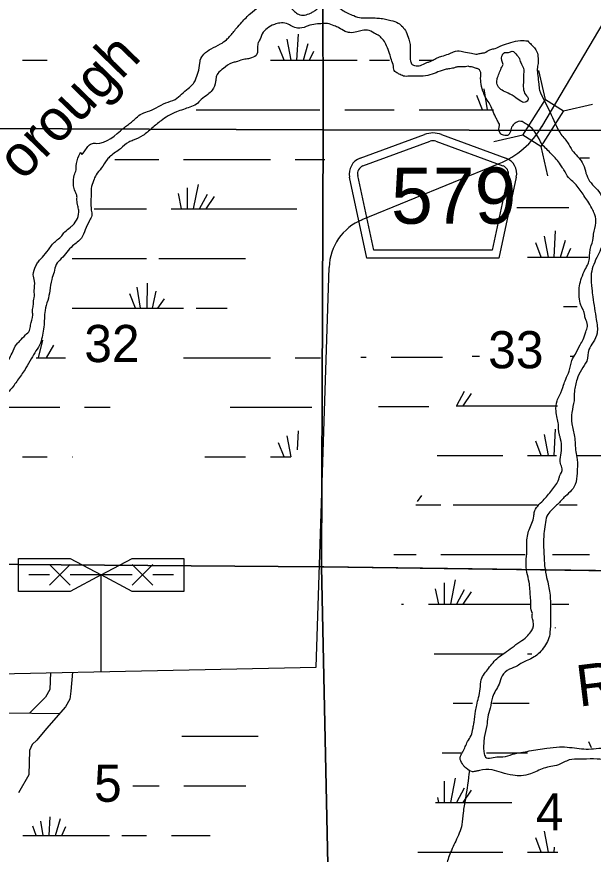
# Model space of a CAD drawing. Extents: x 380424 to 701066, y 1117407 to 1412949.
# Drawn here: x 549442 to 556420, y 1359814 to 1369950 of the extents above; entities that cross this region are included whole.
import ezdxf

# ---------------------------------------------------------------- set-up
doc = ezdxf.new("R2010")
doc.units = 0
for name, color, linetype in [('Bridges and Drawbridges County Highways', 7, 'Continuous'), ('County Routes Highway Center Lines', 7, 'Continuous'), ('Islands', 7, 'Continuous'), ('Local Roads Improved', 7, 'Continuous'), ('Local Roads Paved', 7, 'Continuous'), ('Local Roads Related Cells', 7, 'Continuous'), ('Narrow River Creek and Branch and Slough', 7, 'Continuous'), ('Narrow River Creek and Branch and Slough Text', 7, 'Continuous'), ('Roadshields County Roads', 7, 'Continuous'), ('Section Lines', 7, 'Continuous'), ('Section Numbers', 7, 'Continuous'), ('Swamps', 7, 'Continuous'), ('Township  and Range lines', 7, 'Continuous'), ('Wide Rivers and Canals', 7, 'Continuous')]:
    doc.layers.add(name, color=color, linetype=linetype)

msp = doc.modelspace()

# ---------------------------------------------------------------- linework, layer by layer
at = {"layer": 'Bridges and Drawbridges County Highways'}
for p, q in [((555842, 1368948), (555761, 1369301)), ((556058, 1368812), (556411, 1368892)), ((555569, 1368515), (555216, 1368435)), ((555785, 1368378), (555865, 1368025))]:
    msp.add_line(p, q, dxfattribs=at)
msp.add_lwpolyline([(555569, 1368515), (555842, 1368948), (556058, 1368812), (555785, 1368378)], close=True, dxfattribs=at)
at = {"layer": 'County Routes Highway Center Lines'}
for p, q in [((555799, 1368619), (564285, 1382989)), ((553622, 1367494), (555281, 1368172))]:
    msp.add_line(p, q, dxfattribs=at)
msp.add_lwpolyline([(547296, 1361959), (553065, 1362077), (553222, 1366917)], dxfattribs=at)
for centre, radius, start, end in [((554874, 1369165), 1073, 292.2404, 329.4344), ((553867, 1366896), 645, 112.2402, 178.1451)]:
    msp.add_arc(centre, radius, start, end, dxfattribs=at)
at = {"layer": 'Islands'}
msp.add_spline([(555328, 1369372), (555273, 1369247), (555262, 1369215), (555252, 1369162), (555273, 1369099), (555410, 1369014), (555463, 1368983), (555537, 1368930), (555595, 1368914), (555632, 1368951), (555600, 1369009), (555574, 1369083), (555574, 1369173), (555574, 1369231), (555574, 1369326), (555542, 1369395), (555521, 1369453), (555495, 1369484), (555437, 1369532), (555394, 1369516), (555347, 1369516), (555315, 1369474), (555328, 1369372)], degree=3, dxfattribs=at)
at = {"layer": 'Local Roads Improved'}
msp.add_line((550464, 1362024), (550464, 1363195), dxfattribs=at)
at = {"layer": 'Local Roads Paved'}
for points in [[(549274, 1362000), (549288, 1361524), (549965, 1361519)], [(550117, 1362017), (550096, 1361786), (550083, 1361691), (550034, 1361597), (549804, 1361338), (549685, 1361194), (549628, 1361141), (549595, 1361071), (549587, 1360775), (549463, 1360557)], [(549850, 1362012), (549841, 1361806), (549792, 1361716), (549598, 1361521)]]:
    msp.add_lwpolyline(points, dxfattribs=at)
at = {"layer": 'Local Roads Related Cells'}
for p, q in [((549464, 1363395), (550089, 1363395)), ((549464, 1362995), (549464, 1363395)), ((549839, 1363070), (550089, 1363320)), ((550089, 1363070), (549839, 1363320)), ((550089, 1363395), (550464, 1363195)), ((550464, 1363195), (550839, 1363395)), ((550839, 1363395), (551464, 1363395)), ((551089, 1363072), (550839, 1363322)), ((550839, 1363070), (551089, 1363320)), ((551464, 1363395), (551464, 1362995)), ((549839, 1363195), (549589, 1363195)), ((550464, 1363195), (550089, 1362995)), ((550839, 1363195), (550089, 1363195)), ((550839, 1362995), (550464, 1363195)), ((551339, 1363195), (551089, 1363195)), ((550089, 1362995), (549464, 1362995)), ((551464, 1362995), (550839, 1362995))]:
    msp.add_line(p, q, dxfattribs=at)
at = {"layer": 'Narrow River Creek and Branch and Slough'}
msp.add_spline([(554921, 1360827), (554872, 1360485), (554845, 1360316), (554829, 1360173), (554755, 1359973), (554676, 1359793), (554629, 1359640), (554597, 1359524), (554587, 1359403), (554581, 1359281), (554565, 1359160), (554565, 1359049), (554555, 1358922), (554523, 1358780), (554481, 1358680), (554428, 1358595), (554338, 1358495), (554238, 1358373), (554127, 1358178), (553980, 1358046), (553805, 1357914), (553700, 1357798), (553594, 1357698), (553473, 1357619), (553362, 1357587), (553177, 1357545), (553040, 1357508), (552950, 1357481), (552792, 1357471), (552628, 1357492), (552528, 1357508), (552438, 1357497), (552359, 1357481), (552248, 1357450), (552158, 1357402), (552074, 1357349), (551895, 1357254), (551757, 1357186), (551599, 1357123), (551472, 1357075), (551346, 1357043), (551224, 1357012), (551145, 1356991), (551013, 1356964), (550776, 1356932), (550649, 1356932), (550438, 1356954), (550374, 1356964), (550253, 1356980), (550105, 1357022), (550021, 1357075), (549926, 1357154), (549773, 1357260), (549667, 1357334), (549540, 1357423), (549356, 1357529), (549197, 1357608), (549055, 1357666), (548918, 1357708), (548722, 1357761), (548553, 1357798), (548448, 1357830), (548300, 1357877), (548168, 1357914), (548015, 1357946), (547909, 1357967), (547820, 1357978), (547725, 1357993), (547640, 1358025), (547566, 1358067), (547455, 1358189), (547376, 1358289), (547334, 1358342), (547165, 1358505), (547102, 1358590), (547065, 1358653), (546975, 1358732), (546901, 1358764), (546811, 1358790), (546690, 1358806), (546484, 1358796), (546342, 1358790), (546199, 1358801), (546109, 1358827), (546020, 1358854), (545940, 1358852), (545818, 1358840), (545648, 1358809), (545570, 1358785), (545472, 1358743), (545387, 1358706), (545315, 1358688), (545254, 1358670), (545157, 1358639), (545004, 1358566)], degree=3, dxfattribs=at)
at = {"layer": 'Roadshields County Roads'}
for p, q in [((553598, 1368238), (554377, 1368525)), ((554584, 1368525), (555362, 1368239)), ((553632, 1368144), (554446, 1368443)), ((554515, 1368443), (555327, 1368145)), ((553681, 1367026), (553471, 1368009)), ((553762, 1367126), (553569, 1368029)), ((555391, 1368030), (555197, 1367126)), ((555488, 1368009), (555278, 1367026)), ((555197, 1367126), (553762, 1367126)), ((555278, 1367026), (553681, 1367026))]:
    msp.add_line(p, q, dxfattribs=at)
for centre, radius, start, end in [((554480, 1368243), 300, 69.8262, 110.1722), ((554480, 1368349), 100, 69.8262, 110.1722), ((553667, 1368050), 200, 110.1722, 192.0991), ((555293, 1368051), 200, 347.8993, 69.8262), ((553667, 1368050), 100, 110.1722, 192.0991), ((555293, 1368051), 100, 347.8993, 69.8262)]:
    msp.add_arc(centre, radius, start, end, dxfattribs=at)
at = {"layer": 'Section Lines'}
for points in [[(553140, 1373844), (553151, 1368591), (553151, 1368582), (547887, 1368603), (547887, 1368608), (547882, 1373902)], [(558414, 1373917), (558449, 1368570), (553151, 1368582), (553151, 1368591), (553140, 1373844)], [(553151, 1368582), (553132, 1363292), (547875, 1363334), (547887, 1368603)], [(558449, 1368570), (558542, 1363220), (553159, 1363292), (553132, 1363292), (553151, 1368582)], [(553132, 1363292), (553244, 1357982), (553243, 1357961), (547939, 1358045), (547875, 1363334)], [(558542, 1363220), (558555, 1357902), (553243, 1357961), (553244, 1357982), (553132, 1363292), (553159, 1363292)]]:
    msp.add_lwpolyline(points, close=True, dxfattribs=at)
at = {"layer": 'Swamps'}
for p, q in [((552834, 1369423), (552851, 1369739)), ((552678, 1369423), (552612, 1369595)), ((552763, 1369423), (552717, 1369677)), ((552911, 1369423), (552969, 1369627)), ((552987, 1369423), (553036, 1369532)), ((549512, 1369423), (549812, 1369423)), ((552512, 1369423), (553562, 1369423)), ((553712, 1369423), (553955, 1369423)), ((554312, 1369423), (554485, 1369423)), ((555078, 1368824), (555012, 1368997)), ((555140, 1368823), (555101, 1369076)), ((551612, 1368823), (553112, 1368823)), ((553412, 1368823), (554012, 1368823)), ((554312, 1368823), (554912, 1368823)), ((554912, 1368823), (555214, 1368823)), ((550712, 1368223), (551162, 1368223)), ((551462, 1368223), (552512, 1368223)), ((556260, 1368241), (556375, 1368241)), ((551503, 1367881), (551503, 1367623)), ((551636, 1367918), (551577, 1367623)), ((551395, 1367809), (551432, 1367623)), ((551745, 1367797), (551651, 1367622)), ((551830, 1367773), (551730, 1367624)), ((550712, 1367623), (551012, 1367623)), ((555876, 1367041), (555829, 1367295)), ((555947, 1367041), (555964, 1367357)), ((555791, 1367041), (555725, 1367213)), ((556023, 1367041), (556082, 1367245)), ((556100, 1367041), (556149, 1367149)), ((550112, 1367023), (550712, 1367023)), ((550712, 1367023), (551012, 1367023)), ((551162, 1367023), (552212, 1367023)), ((555625, 1367041), (556359, 1367041)), ((550940, 1366423), (550901, 1366676)), ((551019, 1366423), (551024, 1366727)), ((550878, 1366424), (550812, 1366597)), ((551086, 1366423), (551129, 1366629)), ((551148, 1366422), (551232, 1366536)), ((550112, 1366423), (550712, 1366423)), ((550712, 1366423), (551462, 1366423)), ((549889, 1365977), (549799, 1365823)), ((551462, 1365823), (552512, 1365823)), ((553972, 1365831), (554422, 1365831)), ((554955, 1365841), (555043, 1365841)), ((556142, 1365841), (556192, 1365841)), ((554942, 1365390), (554843, 1365242)), ((549212, 1365223), (549962, 1365223)), ((553822, 1365231), (554422, 1365231)), ((555947, 1364641), (555964, 1364957)), ((555876, 1364641), (555829, 1364895)), ((552678, 1364623), (552612, 1364795)), ((555791, 1364641), (555725, 1364813)), ((555625, 1364641), (555975, 1364641)), ((556223, 1364641), (556675, 1364641)), ((549512, 1364623), (549812, 1364623)), ((554725, 1364041), (555740, 1364041)), ((556012, 1364041), (556225, 1364041)), ((554575, 1363441), (555597, 1363441)), ((555925, 1363441), (556375, 1363441)), ((554749, 1363136), (554690, 1362841)), ((554507, 1363027), (554545, 1362841)), ((554616, 1363099), (554616, 1362841)), ((554858, 1363015), (554764, 1362840)), ((554942, 1362991), (554843, 1362842)), ((554425, 1362841), (555652, 1362841)), ((555919, 1362841), (556125, 1362841)), ((555964, 1362550), (555964, 1362557)), ((555625, 1362241), (555678, 1362241)), ((554725, 1361641), (554958, 1361641)), ((555200, 1361641), (555642, 1361641)), ((551914, 1361242), (552364, 1361242)), ((554616, 1360699), (554616, 1360441)), ((554749, 1360736), (554690, 1360441)), ((551464, 1360642), (551914, 1360642)), ((551914, 1360642), (552214, 1360642)), ((554858, 1360615), (554764, 1360440)), ((554942, 1360591), (554843, 1360442)), ((549912, 1360042), (549970, 1360246)), ((549989, 1360042), (550038, 1360151)), ((549514, 1360042), (550564, 1360042)), ((550714, 1360042), (551014, 1360042)), ((555791, 1359841), (555725, 1360013))]:
    msp.add_line(p, q, dxfattribs=at)
for points in [[(550629, 1368223), (550712, 1368223)], [(552812, 1368223), (553170, 1368223)], [(550378, 1367623), (550712, 1367623)], [(551312, 1367623), (552834, 1367623)], [(555495, 1367641), (556125, 1367641)], [(555325, 1367041), (555325, 1367041)], [(551612, 1366423), (551987, 1366423)], [(556059, 1366441), (556225, 1366441)], [(549756, 1366037), (549702, 1365823)], [(549677, 1365823), (550033, 1365823)], [(552812, 1365823), (553117, 1365823)], [(553607, 1365831), (553672, 1365831)], [(554422, 1365831), (554595, 1365831)], [(554858, 1365415), (554764, 1365240)], [(554762, 1365241), (555988, 1365241)], [(550262, 1365223), (550574, 1365223)], [(552026, 1365223), (553012, 1365223)], [(554422, 1365231), (554430, 1365231)], [(552839, 1364709), (552851, 1364939)], [(552763, 1364625), (552717, 1364877)], [(554530, 1364641), (555325, 1364641)], [(550112, 1364623), (550117, 1364623)], [(551719, 1364623), (552212, 1364623)], [(552512, 1364623), (552761, 1364623)], [(554293, 1364084), (554344, 1364154)], [(554274, 1364041), (554575, 1364041)], [(554005, 1363441), (554275, 1363441)], [(554099, 1362841), (554125, 1362841)], [(554495, 1362241), (555325, 1362241)], [(551442, 1361242), (551914, 1361242)], [(556363, 1361177), (556393, 1361106)], [(554591, 1361041), (554816, 1361041)], [(555126, 1361041), (555625, 1361041)], [(550846, 1360642), (551164, 1360642)], [(554533, 1360500), (554545, 1360441)], [(554512, 1360441), (555434, 1360441)], [(549764, 1360042), (549733, 1360213)], [(549835, 1360042), (549848, 1360269)], [(549679, 1360042), (549637, 1360153)], [(555876, 1359841), (555829, 1360095)], [(551314, 1360042), (551784, 1360042)], [(555947, 1359841), (555950, 1359899)], [(554296, 1359841), (555325, 1359841)], [(555625, 1359841), (555989, 1359841)]]:
    msp.add_lwpolyline(points, dxfattribs=at)
at = {"layer": 'Township  and Range lines'}
for p, q in [((547875, 1363334), (553132, 1363292)), ((553132, 1363292), (553159, 1363292)), ((553159, 1363292), (558542, 1363220))]:
    msp.add_line(p, q, dxfattribs=at)
at = {"layer": 'Wide Rivers and Canals'}
for points in [[(550023, 1367345), (550092, 1367403), (550118, 1367425), (550192, 1367609), (550187, 1367636), (550181, 1367662), (550171, 1367731), (550171, 1367773), (550150, 1367836), (550129, 1367905), (550129, 1367926), (550139, 1368031), (550160, 1368095), (550160, 1368147), (550224, 1368295), (550224, 1368290), (550276, 1368337), (550313, 1368390), (550361, 1368417), (550403, 1368417), (550736, 1368601), (550783, 1368638), (550831, 1368675), (550873, 1368712), (550936, 1368765), (551026, 1368802), (551131, 1368849), (551247, 1368907), (551358, 1368950), (551437, 1369013), (551517, 1369081), (551580, 1369140), (551606, 1369187), (551638, 1369277), (551659, 1369388), (551664, 1369424), (551707, 1369498), (551796, 1369562), (551907, 1369620), (551981, 1369672), (552018, 1369709), (552102, 1369810), (552166, 1369884), (552271, 1369989), (552482, 1370132), (552535, 1370158), (552604, 1370184), (552678, 1370153), (552730, 1370089), (552773, 1370047), (552804, 1370015), (552852, 1369979), (552999, 1369994), (553036, 1370015), (553068, 1370037), (553147, 1370095), (553242, 1370105), (553300, 1370084), (553390, 1370026), (553448, 1369994), (553522, 1369963), (553612, 1369936), (553670, 1369936), (553765, 1369936), (553833, 1369931), (553907, 1369921), (553970, 1369905), (554060, 1369873), (554113, 1369826), (554155, 1369767), (554187, 1369678), (554203, 1369614), (554203, 1369509), (554208, 1369414), (554229, 1369372), (554292, 1369356), (554329, 1369361), (554398, 1369393), (554435, 1369403), (554472, 1369419), (554530, 1369451), (554588, 1369472), (554667, 1369498), (554730, 1369525), (554820, 1369535), (554852, 1369525), (554947, 1369509), (555015, 1369498), (555063, 1369509), (555105, 1369514), (555168, 1369551), (555216, 1369562), (555284, 1369588), (555321, 1369604), (555422, 1369636), (555538, 1369662), (555627, 1369657)], [(555458, 1368649), (555432, 1368612), (555422, 1368580), (555390, 1368517), (555348, 1368512), (555300, 1368533), (555279, 1368612), (555284, 1368649), (555269, 1368675), (555258, 1368696), (555237, 1368738), (555200, 1368823), (555168, 1368891), (555126, 1368955), (555094, 1369023), (555063, 1369134), (555057, 1369229), (555042, 1369308), (555021, 1369319), (555005, 1369324), (554962, 1369340), (554926, 1369345), (554904, 1369351), (554873, 1369345), (554809, 1369345), (554767, 1369340), (554730, 1369329), (554667, 1369319), (554614, 1369308), (554419, 1369240), (554176, 1369229), (554139, 1369229), (554081, 1369250), (554044, 1369271), (554018, 1369287), (554002, 1369351), (553976, 1369430), (553955, 1369504), (553918, 1369599), (553881, 1369667), (553860, 1369688), (553828, 1369720), (553786, 1369741), (553707, 1369783), (553622, 1369783), (553559, 1369767), (553474, 1369757), (553416, 1369773), (553342, 1369815), (553284, 1369841), (553205, 1369868), (553158, 1369868), (553084, 1369862), (552989, 1369847), (552947, 1369831), (552841, 1369810), (552773, 1369836), (552709, 1369868), (552625, 1369873), (552561, 1369857), (552535, 1369847), (552456, 1369794), (552424, 1369762), (552387, 1369678), (552366, 1369636), (552356, 1369578), (552350, 1369498), (552282, 1369451), (552234, 1369440), (552171, 1369430), (552097, 1369403), (552050, 1369393), (551944, 1369324), (551875, 1369261), (551854, 1369208), (551849, 1369166), (551807, 1369060), (551754, 1369008), (551675, 1368950), (551617, 1368891), (551538, 1368855), (551459, 1368828), (551374, 1368797), (551274, 1368749), (551189, 1368691), (551079, 1368601), (550968, 1368512), (550852, 1368454), (550799, 1368432), (550699, 1368353), (550577, 1368264), (550535, 1368221), (550466, 1368116), (550403, 1368037), (550371, 1367963), (550345, 1367873), (550345, 1367820)], [(555627, 1369657), (555670, 1369614), (555738, 1369525), (555751, 1369449), (555751, 1369384), (555742, 1369317), (555748, 1369238), (555759, 1369134), (555771, 1369061), (555823, 1368944), (555960, 1368656)], [(555800, 1368402), (555622, 1368643), (555585, 1368665), (555559, 1368680), (555495, 1368675), (555458, 1368649)], [(555960, 1368656), (556018, 1368543), (556108, 1368427), (556166, 1368332), (556287, 1368184), (556361, 1367984), (556503, 1367810), (556551, 1367699), (556588, 1367567), (556582, 1367467), (556567, 1367351), (556546, 1367240), (556509, 1367134), (556461, 1367034), (556393, 1366812), (556403, 1366659), (556414, 1366559), (556435, 1366422), (556456, 1366285), (556466, 1366121), (556419, 1366010), (556366, 1365921), (556340, 1365783), (556276, 1365678), (556224, 1365562), (556192, 1365414), (556187, 1365303), (556160, 1365161), (556160, 1365024), (556192, 1364870), (556208, 1364686), (556224, 1364591), (556224, 1364427), (556202, 1364290), (556139, 1364200), (556065, 1364132), (555976, 1364037), (555859, 1363905), (555838, 1363805), (555823, 1363694), (555817, 1363551), (555823, 1363446), (555828, 1363340), (555849, 1363192), (555875, 1363082), (555891, 1362997), (555902, 1362812), (555902, 1362649), (555896, 1362501), (555875, 1362411), (555828, 1362327), (555770, 1362253), (555627, 1362163), (555559, 1362132), (555501, 1362095), (555406, 1362053), (555316, 1361973), (555279, 1361873), (555200, 1361715), (555173, 1361583), (555142, 1361472), (555131, 1361372), (555100, 1361229), (555094, 1361156), (555100, 1361029), (555126, 1360981), (555210, 1360987), (555295, 1360992), (555326, 1360992), (555443, 1361024), (555543, 1361045), (555749, 1361082), (555859, 1361097), (556012, 1361113), (556134, 1361108), (556361, 1361087), (556487, 1361097), (556709, 1361108), (556830, 1361108), (556920, 1361087), (557036, 1360987), (557121, 1360960), (557195, 1360950), (557242, 1360960), (557295, 1360987), (557311, 1360997)], [(554857, 1360876), (554836, 1360908), (554809, 1360981), (554841, 1361055), (554899, 1361177), (554941, 1361251), (554962, 1361330), (554973, 1361388), (554978, 1361414), (554994, 1361546), (555010, 1361620), (555031, 1361710), (555052, 1361815), (555063, 1361926), (555105, 1362000), (555152, 1362063), (555268, 1362195), (555348, 1362253), (555437, 1362316), (555532, 1362385), (555617, 1362448), (555664, 1362506), (555691, 1362554), (555696, 1362607), (555691, 1362638), (555680, 1362691), (555680, 1362739), (555675, 1362749), (555664, 1362839), (555664, 1362844), (555659, 1362934), (555643, 1363108), (555617, 1363224), (555606, 1363356), (555617, 1363483), (555622, 1363662), (555675, 1363820), (555701, 1363905), (555706, 1363952), (555812, 1364095), (555918, 1364221), (556002, 1364353), (556013, 1364390), (556044, 1364480), (556023, 1364543), (556028, 1364644), (556018, 1364865), (556007, 1364902), (555997, 1365018), (555981, 1365092), (555970, 1365177), (555981, 1365303), (556013, 1365367), (556060, 1365493), (556086, 1365562), (556129, 1365662), (556160, 1365789), (556203, 1365868), (556261, 1365979), (556298, 1366042), (556329, 1366137), (556350, 1366200), (556334, 1366274), (556319, 1366316), (556313, 1366353), (556303, 1366390), (556271, 1366459), (556250, 1366559), (556250, 1366670), (556271, 1366765), (556308, 1366865), (556350, 1366944), (556371, 1367002), (556377, 1367087), (556387, 1367150), (556419, 1367271), (556424, 1367319), (556451, 1367456), (556440, 1367551), (556414, 1367609), (556366, 1367699), (556319, 1367768), (556224, 1367899), (556171, 1367957), (556118, 1368005), (556065, 1368095), (556039, 1368132), (556023, 1368158), (555912, 1368290), (555800, 1368402)], [(550345, 1367820), (550340, 1367720), (550345, 1367609), (550350, 1367546), (550324, 1367483), (550271, 1367372), (550224, 1367271), (550118, 1367176), (549981, 1367023), (549918, 1366950), (549896, 1366860), (549865, 1366770), (549844, 1366633), (549817, 1366517), (549786, 1366396), (549770, 1366195), (549754, 1366095), (549728, 1366000), (549675, 1365905), (549617, 1365810), (549553, 1365699), (549464, 1365567), (549374, 1365446), (549274, 1365345), (549121, 1365229), (549015, 1365134), (548989, 1365071), (548989, 1365034), (549023, 1364993), (549087, 1364859), (549087, 1364719), (548975, 1364610), (548854, 1364492), (548753, 1364400), (548667, 1364350), (548560, 1364271), (548432, 1364200), (548308, 1364126), (548289, 1364121), (548189, 1364057), (548089, 1364064), (547989, 1364093), (547918, 1364105), (547828, 1364111), (547738, 1364100), (547701, 1364068), (547627, 1364026), (547564, 1363973), (547511, 1363936), (547390, 1363815), (547332, 1363752), (547168, 1363678), (547094, 1363662), (547020, 1363657), (546941, 1363673), (546883, 1363704), (546836, 1363725), (546757, 1363773), (546704, 1363820), (546614, 1363884), (546588, 1363910), (546530, 1363968), (546472, 1364021), (546408, 1364063), (546340, 1364095), (546250, 1364121), (546187, 1364137), (546113, 1364153), (546055, 1364158), (545997, 1364153), (545918, 1364158), (545828, 1364163), (545553, 1364116), (545179, 1364000), (544978, 1363936), (544883, 1363936), (544794, 1363921), (544709, 1363921), (544598, 1363942), (544535, 1363963), (544472, 1364016), (544445, 1364047), (544414, 1364095), (544392, 1364132), (544366, 1364195), (544334, 1364227), (544303, 1364264), (544266, 1364306), (544208, 1364374), (544166, 1364443), (544123, 1364512), (544102, 1364554), (544079, 1364605), (544038, 1364667), (543966, 1364705), (543883, 1364729), (543780, 1364743)], [(544143, 1364884), (544193, 1364839), (544266, 1364766), (544284, 1364648), (544356, 1364540), (544487, 1364476), (544533, 1364453), (544678, 1364367), (544750, 1364263), (544827, 1364227), (544920, 1364184), (545036, 1364184), (545110, 1364195), (545268, 1364248), (545321, 1364274), (545437, 1364316), (545527, 1364343), (545701, 1364396), (545817, 1364406), (545976, 1364406), (546086, 1364385), (546229, 1364374), (546308, 1364348), (546419, 1364290), (546451, 1364274), (546561, 1364200), (546630, 1364142), (546662, 1364095), (546699, 1364053), (546709, 1364042), (546741, 1364016), (546815, 1363963), (546915, 1363910), (546978, 1363889), (547057, 1363863), (547137, 1363889), (547179, 1363894), (547216, 1363926), (547237, 1363958), (547300, 1364042), (547363, 1364126), (547400, 1364169), (547448, 1364227), (547532, 1364311), (547622, 1364332), (547722, 1364338), (547775, 1364343), (547911, 1364314), (547968, 1364314), (548082, 1364278), (548132, 1364278), (548201, 1364304), (548295, 1364358), (548359, 1364398), (548532, 1364521), (548588, 1364554), (548644, 1364589), (548729, 1364649), (548814, 1364740), (548881, 1364813), (548872, 1364886), (548857, 1364946), (548841, 1364997), (548820, 1365047), (548802, 1365092), (548794, 1365134), (548799, 1365235), (548820, 1365287), (548852, 1365319), (548904, 1365335), (548999, 1365393), (549042, 1365414), (549100, 1365461), (549168, 1365530), (549237, 1365609), (549311, 1365736), (549385, 1365878), (549443, 1365989), (549480, 1366026), (549548, 1366100), (549596, 1366153), (549610, 1366217), (549636, 1366341), (549633, 1366394), (549643, 1366452), (549647, 1366513), (549654, 1366549), (549654, 1366638), (549659, 1366749), (549643, 1366828), (549675, 1366934), (549701, 1366981), (549770, 1367060), (549844, 1367155), (549886, 1367208), (549986, 1367298), (550023, 1367345)], [(562535, 1362902), (562498, 1362960), (562440, 1363045), (562424, 1363066), (562377, 1363119), (562345, 1363150), (562276, 1363171), (562245, 1363187), (562229, 1363192), (562134, 1363187), (562055, 1363187), (561997, 1363187), (561912, 1363161), (561833, 1363119), (561759, 1363034), (561659, 1362913), (561606, 1362860), (561574, 1362823), (561527, 1362765), (561437, 1362638), (561395, 1362564), (561332, 1362454), (561290, 1362322), (561284, 1362243), (561290, 1362047), (561295, 1361984), (561295, 1361868), (561247, 1361757), (561184, 1361615), (561136, 1361583), (561068, 1361551), (560989, 1361514), (560904, 1361483), (560788, 1361462), (560688, 1361446), (560577, 1361419), (560466, 1361330), (560387, 1361235), (560313, 1361171), (560271, 1361150), (560213, 1361134), (560144, 1361119), (560034, 1361103), (559949, 1361098), (559812, 1361092), (559828, 1361108), (559712, 1361134), (559633, 1361166), (559527, 1361203), (559411, 1361224), (559300, 1361235), (559242, 1361229), (559152, 1361208), (559084, 1361182), (559015, 1361161), (558899, 1361171), (558730, 1361214), (558635, 1361229), (558530, 1361240), (558387, 1361277), (558208, 1361367), (558086, 1361372), (557976, 1361351), (557907, 1361330), (557865, 1361293), (557822, 1361256), (557754, 1361166), (557701, 1361082), (557648, 1360992), (557590, 1360913), (557511, 1360855), (557416, 1360802), (557332, 1360781), (557242, 1360781), (557089, 1360807), (556989, 1360834), (556925, 1360860), (556841, 1360913), (556741, 1360939), (556603, 1360955), (556466, 1360966), (556297, 1360966), (556260, 1360966), (556129, 1360955), (555997, 1360897), (555907, 1360876), (555822, 1360855), (555659, 1360786), (555548, 1360765), (555448, 1360770), (555311, 1360802), (555195, 1360834), (555041, 1360828), (554999, 1360818), (554957, 1360813), (554883, 1360855), (554857, 1360876)]]:
    msp.add_spline(points, degree=3, dxfattribs=at)

# ---------------------------------------------------------------- texts
at = {"layer": 'Narrow River Creek and Branch and Slough Text'}
for s, rotation, p in [('orough', 45.854, (549515, 1367952)), ('River', 6.9812, (556247, 1361599))]:
    msp.add_text(s, height=500, rotation=rotation, dxfattribs=at).set_placement(p)
at = {"layer": 'Roadshields County Roads'}
msp.add_text('579', height=680, rotation=359.9992, dxfattribs=at).set_placement((553972, 1367445))
at = {"layer": 'Section Numbers'}
for s, p in [('32', (550260, 1365770)), ('33', (555148, 1365695)), ('5', (550378, 1360449)), ('4', (555726, 1360103))]:
    msp.add_text(s, height=450, dxfattribs=at).set_placement(p)

doc.saveas('drawing.dxf')
